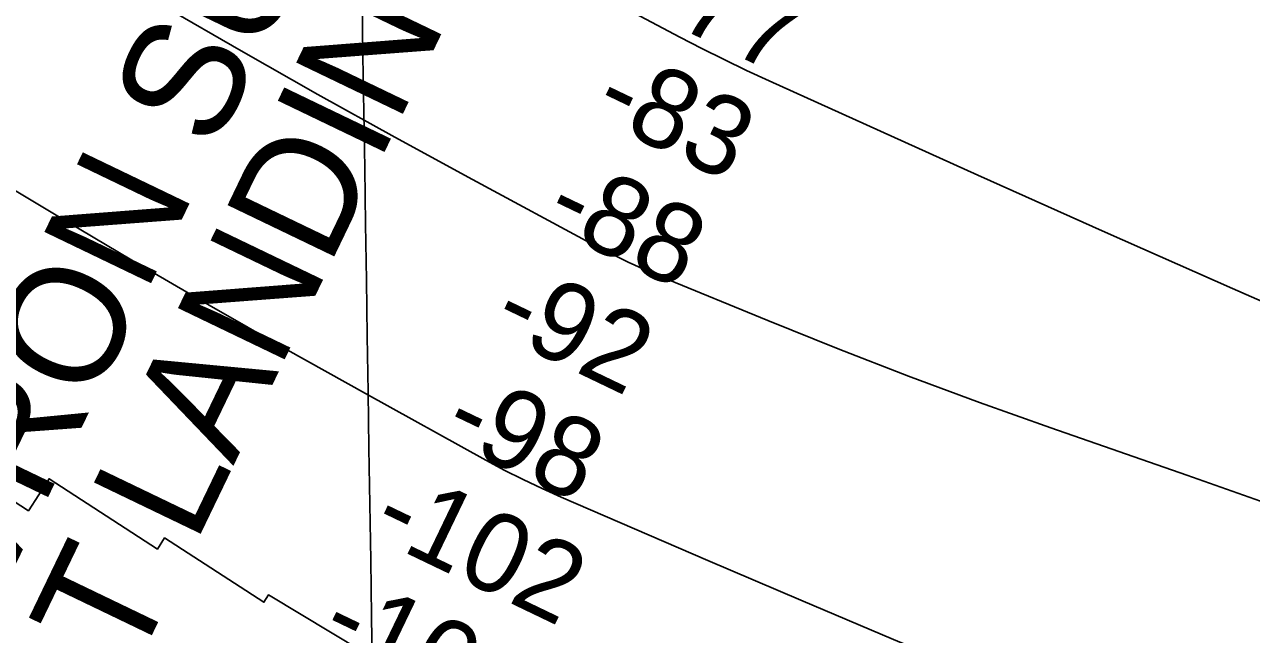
# Model space of a CAD drawing. Extents: x 3823584 to 3861785, y 301729 to 327625.
# Drawn here: x 3843247 to 3844284, y 321302 to 321817 of the extents above; entities that cross this region are included whole.
import ezdxf

# ---------------------------------------------------------------- set-up
doc = ezdxf.new("R2010")
doc.units = 0
for name, color, linetype in [('V-CHAN-NAID', 7, 'Continuous'), ('V-GRID-MAJR', 7, 'Continuous'), ('V-RIVR-RANG', 7, 'Continuous'), ('V-RRAP-RVMT', 7, 'Continuous'), ('V-TOPO-MAJR', 7, 'Continuous'), ('V-TOPO-MINR', 7, 'Continuous')]:
    doc.layers.add(name, color=color, linetype=linetype)

msp = doc.modelspace()

# ---------------------------------------------------------------- linework, layer by layer
at = {"layer": 'V-GRID-MAJR'}
msp.add_spline([(3843755.052, 307401.218), (3843661.667, 313457.842), (3843568.228, 319517.936), (3843474.79, 325578.025), (3843474.736, 325581.498)], degree=3, dxfattribs=at)
at = {"layer": 'V-RRAP-RVMT'}
msp.add_lwpolyline([(3843159.2761594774, 321465.65030019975), (3843250.6941061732, 321406.28891182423), (3843268.2357916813, 321433.3008781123), (3843359.65883457, 321373.9303661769), (3843365.774687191, 321383.36505986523), (3843449.695485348, 321328.8672673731), (3843453.4827286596, 321335.17217344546), (3843559.7714862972, 321271.3074720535), (3843547.618440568, 321251.08139875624), (3843628.1901070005, 321202.6690780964), (3843637.1565567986, 321217.5870779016), (3843743.4453143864, 321153.7223774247), (3843742.888167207, 321152.79512840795), (3843837.178570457, 321096.1397633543), (3843843.4943155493, 321106.655422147), (3843950.671554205, 321042.28436054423), (3843961.5915021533, 321060.501650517), (3844068.7398287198, 320996.1224957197), (3844069.9029670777, 320998.06169980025), (3844177.0492962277, 320933.68429894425), (3844185.9400018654, 320948.47925866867), (3844293.085021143, 320884.0928158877)], dxfattribs=at)
at = {"layer": 'V-TOPO-MAJR'}
msp.add_lwpolyline([(3844485.016555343, 321092.5280372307), (3844139.1236525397, 321232.476380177), (3844060.2194861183, 321264.7309052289), (3843981.472747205, 321297.36152577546), (3843902.962149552, 321330.55628956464), (3843824.6089794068, 321364.1271488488), (3843700.7941088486, 321417.7028610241), (3843684.581149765, 321425.0011975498), (3843668.5208108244, 321432.6098921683), (3843652.6894020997, 321440.6841239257), (3843637.010613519, 321449.0687137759), (3843535.4752308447, 321505.2887061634), (3843469.3478226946, 321542.3704803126), (3843403.4928488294, 321579.9240742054), (3843338.0465263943, 321618.18539771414), (3843272.8726382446, 321656.918540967), (3842932.7267877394, 321861.5578633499)], dxfattribs=at)
at = {"layer": 'V-TOPO-MINR'}
for points in [[(3844375.456475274, 321546.84738746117), (3844267.599199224, 321594.03089830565), (3844160.0032952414, 321641.8074316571), (3844052.581639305, 321689.97931334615), (3843876.2540842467, 321769.63482984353), (3843857.2150295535, 321778.4551318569), (3843838.2933807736, 321787.5147612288), (3843819.547840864, 321796.9333816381), (3843800.9197068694, 321806.59132940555), (3843653.0546856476, 321885.050642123)], [(3844334.5110970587, 321399.05784576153), (3844281.8551334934, 321417.758311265), (3844229.1355130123, 321436.28096492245), (3844114.266294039, 321476.31258249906), (3844054.0710911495, 321497.8437856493), (3843994.122930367, 321520.0262190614), (3843934.5453327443, 321543.1854978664), (3843875.2147772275, 321566.9960069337), (3843786.064150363, 321603.62270568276), (3843771.5993437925, 321609.83069722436), (3843757.2742752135, 321616.3341665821), (3843743.15881362, 321623.28085266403), (3843729.1830900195, 321630.52301656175), (3843625.715029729, 321686.202579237), (3843560.3097093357, 321721.86151859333), (3843495.170174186, 321757.9935099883), (3843430.4293169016, 321794.8350794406), (3843365.9542448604, 321832.14970093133)]]:
    msp.add_lwpolyline(points, dxfattribs=at)

# ---------------------------------------------------------------- texts
at = {"layer": 'V-CHAN-NAID'}
for s, height, p in [('CHEVRON SUNRISE', 100.000002, (3843101.570975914, 321073.1233769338)), ('BOAT LANDING (27.5)', 100.00000199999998, (3843217.5476839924, 321015.3517534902))]:
    msp.add_text(s, height=height, rotation=64.30502811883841, dxfattribs=at).set_placement(p)
at = {"layer": 'V-RIVR-RANG'}
for s, p in [('-77', (3843769.6577951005, 321829.11587238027)), ('-83', (3843725.201628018, 321739.5315510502)), ('-88', (3843684.0745457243, 321648.34885437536)), ('-92', (3843639.618378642, 321558.7655330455)), ('-98', (3843598.015712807, 321467.8111757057)), ('-102', (3843537.8652888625, 321385.7630524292)), ('-102', (3843494.360288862, 321295.7220524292))]:
    msp.add_text(s, height=67.00000000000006, rotation=334.35319444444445, dxfattribs=at).set_placement(p)

doc.saveas('drawing.dxf')
